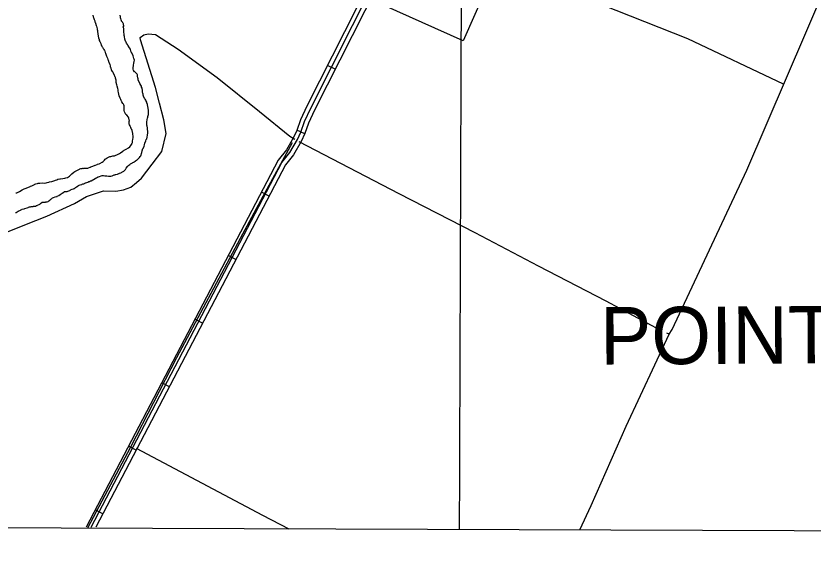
# Model space of a CAD drawing. Extents: x 3146026 to 3183936, y 897894 to 923344.
# Drawn here: x 3153937 to 3156715, y 907250 to 909112 of the extents above; entities that cross this region are included whole.
import ezdxf

# ---------------------------------------------------------------- set-up
doc = ezdxf.new("R2010")
doc.units = 0
for name, color, linetype in [('V-ANNO-SYMB', 7, 'Continuous'), ('V-GRID-MAJR', 7, 'Continuous'), ('V-ROAD-CNTR', 7, 'Continuous'), ('V-TOPO-GNAM-IDEN', 7, 'Continuous'), ('V-TOPO-SHOR', 7, 'Continuous')]:
    doc.layers.add(name, color=color, linetype=linetype)

msp = doc.modelspace()

# ---------------------------------------------------------------- linework, layer by layer
at = {"layer": 'V-ANNO-SYMB'}
msp.add_lwpolyline([(3150260.2, 907341.2), (3165911.3, 907284.3), (3165898.4, 903734.3), (3150247.3, 903791.2)], close=True, dxfattribs=at)
at = {"layer": 'V-GRID-MAJR'}
msp.add_spline([(3155483.1, 907322.2), (3155490.4, 909418.7), (3155511.6, 915481.6), (3155532.8, 921544.5), (3155532.8, 921546.4)], degree=3, dxfattribs=at)
at = {"layer": 'V-ROAD-CNTR'}
for p, q in [((3155049.6, 908926.1), (3155022.8, 908939.7)), ((3154943.6, 908700.9), (3154916.2, 908713.1)), ((3154819.1, 908484.1), (3154792.5, 908498)), ((3154703.3, 908262.5), (3154676.7, 908276.4)), ((3154587.5, 908040.9), (3154560.9, 908054.8)), ((3154471.8, 907819.3), (3154445.2, 907833.2)), ((3154356, 907597.7), (3154329.4, 907611.6)), ((3154240.2, 907376.2), (3154213.6, 907390.1))]:
    msp.add_line(p, q, dxfattribs=at)
for points in [[(3156023.2, 912837.1), (3155997.6, 912795.3), (3155990.4, 912739.3), (3155964.7, 912613.8), (3155957.6, 912539.4), (3155947.8, 912479.6), (3155927.6, 912419.5), (3155902.6, 912342.7), (3155890.4, 912286.7), (3155385.5, 909725.2), (3155372.5, 909641), (3155352.3, 909575.2), (3155326.3, 909519.1), (3155310.2, 909483.9), (3155280.7, 909427.5), (3155236.4, 909348.3), (3155170.2, 909231.7), (3154950.7, 908796.8), (3154928.6, 908749.8), (3154916, 908712.6), (3154904.9, 908687.8), (3154879.8, 908644.6), (3154850.8, 908609.6), (3154182, 907329.4)], [(3154198.8, 907329.4), (3154863.4, 908601.3), (3154892.1, 908635.9), (3154918.2, 908680.9), (3154929.9, 908707.2), (3154942.5, 908744.2), (3154964.2, 908790.2), (3155183.4, 909224.6), (3155249.4, 909341), (3155293.9, 909420.3), (3155323.6, 909477.3), (3155340, 909512.9), (3155366.4, 909569.8), (3155387.2, 909637.7), (3155400.3, 909722.6), (3155905.1, 912283.6), (3155917.1, 912338.8), (3155941.8, 912414.8), (3155962.4, 912475.9), (3155972.4, 912537.5), (3155979.5, 912611.5), (3156005.2, 912736.8), (3156012, 912790.2), (3156036, 912829.2)], [(3156048.8, 912821.4), (3156026.5, 912785.1), (3156020, 912734.4), (3155994.4, 912609.3), (3155987.3, 912535.6), (3155977, 912472.3), (3155956.1, 912410.1), (3155931.6, 912334.9), (3155919.8, 912280.6), (3155415, 909720), (3155401.8, 909634.3), (3155380.4, 909564.4), (3155353.6, 909506.6), (3155337.1, 909470.6), (3155307, 909413.2), (3155262.5, 909333.6), (3155196.7, 909217.6), (3154977.7, 908783.6), (3154956.4, 908738.6), (3154943.9, 908701.7), (3154931.6, 908674.1), (3154904.4, 908627.3), (3154875.9, 908592.9), (3154215.7, 907329.3)]]:
    msp.add_lwpolyline(points, dxfattribs=at)
at = {"layer": 'V-TOPO-SHOR'}
for points in [[(3156213.1, 908002.9), (3156223.8, 908019.3), (3156483.7, 908574.2), (3156760.5, 909218.7), (3156941, 909624.7), (3157082.5, 909925.8), (3157349, 910509.6), (3157396.5, 910605.6), (3157401.4, 910624.3)], [(3156612.1, 908874.2), (3156278, 909032.5), (3155828.4, 909211.3), (3155667.6, 909225.6), (3155605.4, 909231.6), (3155581.9, 909220.6), (3155495.4, 909025.5), (3155165.5, 909173.5), (3155241.5, 909305.1), (3155314.4, 909425.1), (3155336.9, 909455), (3155379.3, 909462.4)], [(3154205, 909114.6), (3154206.6, 909109.2), (3154207.9, 909105.9), (3154209.9, 909099.1), (3154211.6, 909094.6), (3154212.3, 909091.8), (3154213, 909089.7), (3154214.1, 909087.2), (3154217, 909078.9), (3154218, 909075.7), (3154219.8, 909066.5), (3154220.2, 909063.7), (3154220.8, 909061.9), (3154221.7, 909057), (3154222.7, 909050.9), (3154222.5, 909049.9), (3154223.5, 909041.8), (3154224.8, 909035.2), (3154226.6, 909029.9), (3154227.6, 909026.6), (3154229, 909023.1), (3154229.6, 909022.3), (3154230.3, 909020.2), (3154232.4, 909016), (3154234.6, 909010.4), (3154235.5, 909008.5), (3154236.4, 909007.3), (3154237, 909005.9), (3154238.4, 909003.4), (3154241.6, 908998.4), (3154242.3, 908997.5), (3154242.9, 908996.1), (3154243.8, 908994.9), (3154245.4, 908991.6), (3154246.5, 908988.8), (3154248.3, 908984), (3154248.7, 908982.2), (3154252.7, 908971.9), (3154254.5, 908966.5), (3154255.6, 908964.6), (3154257, 908959.7), (3154258, 908957.3), (3154259.2, 908954.7), (3154261, 908948.9), (3154261.6, 908948), (3154263.8, 908942.4), (3154265.2, 908937.9), (3154266, 908933.9)], [(3154345.6, 908933.9), (3154346.4, 908936.6), (3154346.7, 908938.7), (3154347.2, 908940.4), (3154348, 908947.5), (3154349.5, 908953.1), (3154349.8, 908957.3), (3154349.4, 908961), (3154348.3, 908963.6), (3154345.4, 908973.2), (3154344.3, 908976.1), (3154339.6, 908984.1), (3154339.2, 908985.4), (3154338.3, 908987.3), (3154338, 908989.6), (3154335.8, 908996.2), (3154333.4, 909000.7), (3154327.5, 909010.3), (3154325.7, 909012.9), (3154324.8, 909013.9), (3154322.9, 909017), (3154319.8, 909022.6), (3154319.1, 909023.6), (3154317.1, 909031.5), (3154315.9, 909040.1), (3154314.8, 909044.1), (3154313.8, 909048.8), (3154313.2, 909055.1), (3154313.1, 909066), (3154312.9, 909068.1), (3154312.3, 909070.4), (3154311.2, 909072.8), (3154312.6, 909076), (3154312.6, 909078.8), (3154312.4, 909080), (3154312, 909081), (3154312, 909082.1), (3154311.4, 909084.4), (3154310.7, 909086.1), (3154309.8, 909087.7), (3154309.4, 909088.7), (3154307, 909091.5), (3154306.4, 909092.4), (3154305.3, 909093.6), (3154304.8, 909094.4), (3154303.4, 909097.9), (3154302.2, 909102.5), (3154302, 909104.4), (3154301.7, 909105.6), (3154301.7, 909107), (3154301.3, 909109.3), (3154300, 909114.2)], [(3153908.2, 908359.4), (3153967.8, 908383.1), (3154044.4, 908413.6), (3154140.7, 908458), (3154183.5, 908482.2), (3154241.8, 908502.3), (3154285.1, 908501.2), (3154311.7, 908505.3), (3154337.2, 908515.4), (3154356.9, 908531.8), (3154374.2, 908545.8), (3154411.6, 908595.3), (3154445.2, 908639), (3154460.1, 908702.4), (3154453, 908749.5), (3154437.6, 908807.7), (3154423.4, 908862.3), (3154371.2, 909028.6), (3154370.2, 909037), (3154382.5, 909046.3), (3154398.2, 909049.5), (3154423.5, 909047.7), (3154502.8, 908996.2), (3154638.6, 908897.5), (3154786, 908779.3), (3154892, 908692.2), (3154908.6, 908682.2)], [(3154339, 908718.6), (3154338.3, 908720.4), (3154337.5, 908721.9), (3154337.1, 908723.4), (3154335.1, 908727.3), (3154334.7, 908728.6), (3154333, 908732.5), (3154331.7, 908736.2), (3154331.7, 908738.4), (3154332.2, 908742.1), (3154332.2, 908744.7), (3154332.4, 908746), (3154332.2, 908749.2), (3154330.3, 908755.5), (3154328.8, 908758.8), (3154323.5, 908765.5), (3154320.4, 908768.6), (3154317.2, 908772.9), (3154315.1, 908778.1), (3154314.7, 908782.5), (3154314.7, 908789.4), (3154314.5, 908791.1), (3154314.3, 908796.1), (3154313.9, 908798.7), (3154312.9, 908801.5), (3154311.6, 908803.9), (3154309.6, 908806.5), (3154306.4, 908812), (3154304.3, 908817), (3154302.1, 908820.7), (3154301.1, 908822.8), (3154300.2, 908825.4), (3154297.2, 908833), (3154295.5, 908839.1), (3154294.7, 908845.2), (3154293.7, 908849.9), (3154293, 908854.1), (3154292, 908859.3), (3154290.1, 908866.9), (3154288.6, 908871.4), (3154286.9, 908880.1), (3154286.1, 908889.4), (3154285.5, 908890.5), (3154285.3, 908892), (3154284.6, 908894.6), (3154284.2, 908895.7), (3154284.2, 908896.8), (3154283.4, 908898.3), (3154281.9, 908902.2), (3154280.6, 908904.8), (3154276.7, 908912.4), (3154276.1, 908913.3), (3154275.4, 908914.8), (3154274.2, 908916.8), (3154273.7, 908917.9), (3154271.1, 908921.3), (3154270.3, 908922.9), (3154269.9, 908923.9), (3154268.4, 908929.4), (3154267.3, 908931.8), (3154266, 908933.9)], [(3154378.5, 908847), (3154377.9, 908849.6), (3154377.7, 908851.4), (3154377.7, 908854.2), (3154377.3, 908856.4), (3154376.7, 908858.5), (3154376.5, 908860), (3154375.2, 908863.7), (3154374.1, 908867.6), (3154372.6, 908871.1), (3154369.4, 908876.8), (3154363.6, 908888.7), (3154363, 908890.7), (3154362.6, 908893.5), (3154362.2, 908895.2), (3154361.1, 908902.8), (3154360.3, 908906.7), (3154359.2, 908909.1), (3154354.3, 908914.5), (3154351.7, 908916.7), (3154350.6, 908917.4), (3154347.8, 908920), (3154346.5, 908921.5), (3154345.3, 908926.7), (3154345.7, 908930.4), (3154345.6, 908933.9)], [(3154237.3, 908555.3), (3154239, 908555.3), (3154242.2, 908555.1), (3154247.4, 908554.4), (3154251.8, 908554.4), (3154253.9, 908554.1), (3154259.6, 908553), (3154260.9, 908553), (3154262.4, 908553.2), (3154265.2, 908553.8), (3154267.8, 908553.8), (3154272.3, 908554.9), (3154277.1, 908556.8), (3154279.9, 908557.6), (3154282.8, 908558.3), (3154284.3, 908558.9), (3154290.8, 908560.6), (3154295.3, 908562.1), (3154297.1, 908563), (3154298.2, 908563.2), (3154302.5, 908564.9), (3154304.9, 908566.4), (3154306, 908567.2), (3154312.7, 908571.3), (3154314, 908572.4), (3154316, 908573.7), (3154319.3, 908577.1), (3154321.5, 908580.8), (3154326, 908586.8), (3154327.6, 908588.8), (3154330.6, 908591.8), (3154333.7, 908593.9), (3154336.5, 908596.3), (3154340.6, 908599.1), (3154342.8, 908600.1), (3154344.5, 908601.2), (3154347.6, 908602.5), (3154349.1, 908603.6), (3154352.4, 908605.3), (3154353.4, 908606.4), (3154357.1, 908608.7), (3154359.8, 908610.6), (3154364.3, 908614.7), (3154367.8, 908618.6), (3154370.2, 908621.8), (3154371.8, 908624.6), (3154375.3, 908635.9), (3154376.4, 908642.2), (3154377.9, 908645), (3154378.6, 908647.3), (3154380.4, 908650.2), (3154384.3, 908657.5), (3154385, 908662.5), (3154386.1, 908667.9), (3154389.2, 908676.7), (3154391.4, 908680.6), (3154392.9, 908683.9), (3154394.7, 908689), (3154394.7, 908690.6), (3154395.6, 908695.3), (3154395.6, 908698.4), (3154396, 908699.9), (3154396.3, 908702), (3154396.3, 908709.8), (3154395.9, 908716.1), (3154395.5, 908717.6), (3154395.3, 908719.6), (3154395.3, 908722.2), (3154394.7, 908727.2), (3154394.3, 908728.7), (3154393.6, 908730.2), (3154393, 908734.3), (3154392.8, 908736.1), (3154392.8, 908738.7), (3154393.3, 908742.8), (3154396, 908756.6), (3154396.6, 908758.3), (3154397.1, 908761.6), (3154398.8, 908767.9), (3154398.9, 908768.9), (3154399.5, 908772.6), (3154399.6, 908776.9), (3154399.1, 908780.4), (3154398.7, 908782.2), (3154397.9, 908790.6), (3154396.4, 908796.2), (3154395.2, 908801.7), (3154395, 908803.2), (3154393.5, 908808.6), (3154393, 908810.8), (3154391.3, 908814.5), (3154390.9, 908816), (3154390.1, 908817.3), (3154389.8, 908818.4), (3154387.1, 908821.9), (3154385.6, 908824.5), (3154382.1, 908831.9), (3154380.6, 908835.8), (3154380, 908839.9), (3154379.4, 908841.8), (3154378.5, 908847)], [(3153972.3, 908511.9), (3153986.2, 908517), (3153988.2, 908518.1), (3153992.5, 908519.8), (3154002.1, 908524.1), (3154003.4, 908524.9), (3154006.9, 908526), (3154012.3, 908528.1), (3154014.7, 908528.5), (3154014.9, 908528.7), (3154016.8, 908529.2), (3154020.1, 908529.4), (3154028.8, 908529.5), (3154038.3, 908529.2), (3154042, 908530.1), (3154045.9, 908531.4), (3154052.2, 908532.8), (3154054.1, 908533.7), (3154061.7, 908535), (3154072.8, 908537.9), (3154074.5, 908538.8), (3154075.4, 908539.4), (3154079.7, 908540.9), (3154083.4, 908542.4), (3154090.6, 908544.1), (3154092.3, 908544.1), (3154100.3, 908544.9), (3154107.3, 908545.9), (3154111.4, 908547.4), (3154117.2, 908549.1), (3154120.3, 908550.6), (3154124, 908553.8), (3154124.9, 908554.9), (3154128.1, 908558.1), (3154132, 908561.6), (3154138.8, 908566.7), (3154142.5, 908569.3), (3154146.6, 908571.9), (3154154.4, 908575.5), (3154158.6, 908578.1), (3154159.9, 908578.3), (3154162.9, 908579.6), (3154164.9, 908580.2), (3154165.9, 908580.2), (3154167.7, 908580.6), (3154169.4, 908580.9), (3154172, 908580.6), (3154174.2, 908581), (3154180.5, 908581.2), (3154187.2, 908581), (3154190.4, 908582), (3154195.4, 908584.6), (3154197.2, 908585.2), (3154198.5, 908586.1), (3154204.8, 908588.6), (3154212.8, 908591.2), (3154213.9, 908591.8), (3154220, 908594), (3154221.7, 908594.8), (3154227.3, 908596.3), (3154228.9, 908596.9), (3154237.3, 908601.7), (3154241, 908604.7), (3154245.6, 908609), (3154247.8, 908612), (3154250, 908613.9), (3154251.1, 908615.2), (3154255, 908617.4), (3154264.7, 908621.4), (3154267.8, 908622.3), (3154274.3, 908623.7), (3154279.7, 908624.6), (3154280.8, 908624.6), (3154293.2, 908629.7), (3154295.8, 908631.4), (3154298.2, 908632.2), (3154301.4, 908634.6), (3154302.9, 908635.5), (3154308, 908638.9), (3154310.3, 908641.1), (3154312.1, 908641.9), (3154314.7, 908643.8), (3154321.2, 908647.7), (3154329.3, 908652), (3154333.6, 908655), (3154337.3, 908659.7), (3154339.5, 908663.2), (3154340.4, 908664.3), (3154341.3, 908666.9), (3154341.9, 908668.1), (3154342.8, 908671), (3154343.5, 908674), (3154343.5, 908675.1), (3154345, 908682.6), (3154345.5, 908686.8), (3154345.1, 908693.9), (3154344.3, 908698.2), (3154343.9, 908701.9), (3154341.8, 908712.3), (3154340.5, 908715.8), (3154339, 908718.6)], [(3154187.9, 907326.9), (3154337.6, 907610.2), (3154498.2, 907921), (3154719.6, 908337.5), (3154798.9, 908483.5), (3154901.1, 908671)], [(3156184.3, 908015.2), (3155993.3, 908117.7), (3155758.4, 908239.3), (3155537.3, 908355.6), (3155272.7, 908491.6), (3154923.5, 908672.5)], [(3153936.1, 908426.4), (3153937.4, 908427), (3153944.5, 908431.1), (3153953, 908434.9), (3153954.1, 908435.8), (3153957.1, 908436.8), (3153958.9, 908437.7), (3153965.6, 908440), (3153968, 908440.5), (3153976.2, 908442.8), (3153979.3, 908443.8), (3153980.8, 908444.7), (3153984, 908446), (3153987.3, 908446.8), (3153990.1, 908447), (3153995.8, 908447.9), (3153996.8, 908447.9), (3153998.6, 908448.3), (3154000.1, 908448.3), (3154002.7, 908448.9), (3154005.5, 908449.3), (3154009.2, 908450.8), (3154010.7, 908451), (3154012.2, 908451.9), (3154017.7, 908454.2), (3154019.8, 908455.5), (3154021.2, 908456.4), (3154022.7, 908457.9), (3154028.1, 908462.2), (3154031.8, 908462.8), (3154038.1, 908463.2), (3154040, 908463.2), (3154041.6, 908463.4), (3154045.9, 908464.2), (3154049.1, 908465.1), (3154050.7, 908465.7), (3154052, 908466.8), (3154055.4, 908469.1), (3154058.1, 908471.9), (3154058.9, 908472.6), (3154060.9, 908474.5), (3154064.8, 908477.5), (3154067.9, 908479.3), (3154073.9, 908481.2), (3154078.3, 908482), (3154080.7, 908482.9), (3154081.3, 908483.5), (3154086.1, 908485.9), (3154091.5, 908489.3), (3154094.6, 908491.4), (3154098.1, 908494.4), (3154103.7, 908498.1), (3154106.5, 908499.4), (3154116.1, 908500.2), (3154118, 908500.6), (3154125.4, 908503.8), (3154126.7, 908504.2), (3154127.8, 908505.1), (3154133.4, 908507.9), (3154137.8, 908509.1), (3154140, 908510), (3154141.5, 908510.8), (3154144.5, 908513.6), (3154147.8, 908516.2), (3154154.5, 908519.9), (3154155.6, 908520.7), (3154157.3, 908521.4), (3154161, 908523.3), (3154166.2, 908524.8), (3154167.6, 908525), (3154169.9, 908526.1), (3154171.9, 908526.5), (3154173.8, 908527.1), (3154175.8, 908528.2), (3154177.1, 908528.6), (3154179.1, 908529.7), (3154180.1, 908530.5), (3154184.7, 908531.8), (3154187.7, 908532.9), (3154191.4, 908534.6), (3154193.4, 908535.2), (3154196.4, 908536.5), (3154199.2, 908537.3), (3154204.5, 908540.1), (3154206, 908540.8), (3154207.5, 908542.1), (3154213.6, 908545.3), (3154214.5, 908545.9), (3154215.5, 908546.1), (3154217.3, 908547.4), (3154220.8, 908549.3), (3154223.8, 908550.8), (3154225.1, 908551.1), (3154227.9, 908552.3), (3154234.2, 908554.7), (3154237.3, 908555.3)], [(3153936.3, 908494.8), (3153939.7, 908495.6), (3153949.1, 908500.3), (3153958.9, 908505.7), (3153966, 908509.1), (3153969.3, 908510.4), (3153972.3, 908511.9)], [(3155901.7, 907320.7), (3155941.2, 907405.1), (3156064, 907681.4), (3156213.1, 908002.9), (3156204.8, 908006.2)], [(3154356.6, 907604.9), (3154795.9, 907371.8), (3154888.6, 907324.4)]]:
    msp.add_lwpolyline(points, dxfattribs=at)

# ---------------------------------------------------------------- texts
at = {"layer": 'V-TOPO-GNAM-IDEN'}
msp.add_text('POINTE', height=200, rotation=0.3094, dxfattribs=at).set_placement((3155973.3, 907896.5))

doc.saveas('drawing.dxf')
